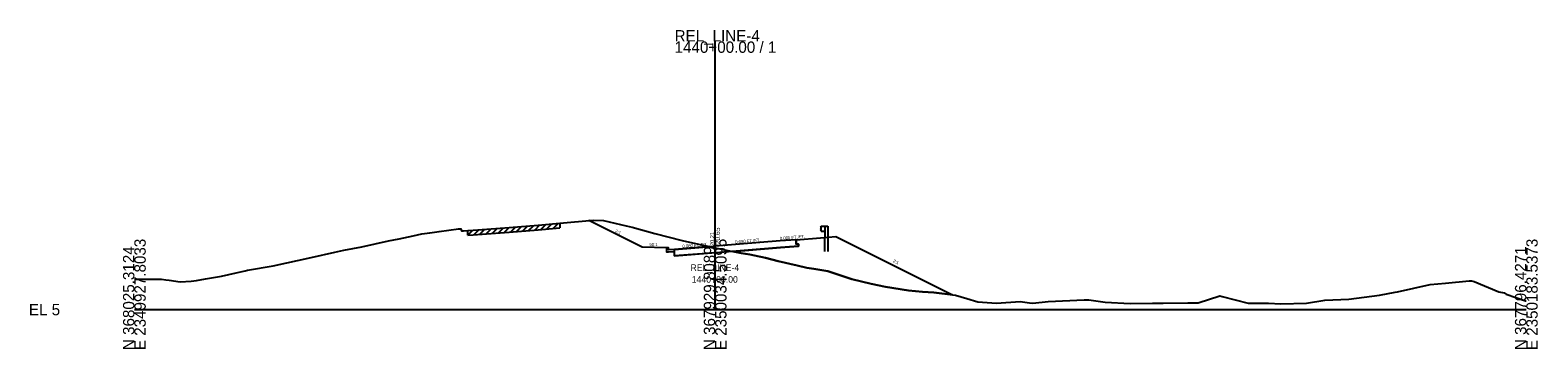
# Model space of a CAD drawing. Extents: x -26 to 2350146, y -10 to 368200.
# Drawn here: x 1974.3 to 2346, y 1490.3 to 1569 of the extents above; entities that cross this region are included whole.
import ezdxf

# ---------------------------------------------------------------- set-up
doc = ezdxf.new("R2010")
doc.units = 0
for name, color, linetype in [('RD_GPK_XS_Cell', 7, 'Continuous'), ('RD_XS_Base', 7, 'Continuous'), ('RD_XS_CurbBase', 7, 'Continuous'), ('RD_XS_CurbFront', 7, 'Continuous'), ('RD_XS_CurbTop', 7, 'Continuous'), ('RD_XS_EarthShd', 7, 'Continuous'), ('RD_XS_EwShp', 7, 'Continuous'), ('RD_XS_ExGround', 7, 'Continuous'), ('RD_XS_ExPaveRet', 7, 'Continuous'), ('RD_XS_GR', 7, 'Continuous'), ('RD_XS_Pave', 7, 'Continuous'), ('RD_XS_PaveShd', 7, 'Continuous'), ('RD_XS_TieSlope', 7, 'Continuous'), ('RD_XS_TX_Elev_EX', 7, 'Continuous'), ('RD_XS_TX_Elev_PR', 7, 'Continuous'), ('RD_XS_TX_Slope', 7, 'Continuous'), ('RD_XS_TX_Station', 7, 'Continuous'), ('RD_XS_TX_TOC', 7, 'Continuous')]:
    doc.layers.add(name, color=color, linetype=linetype)

msp = doc.modelspace()

# ---------------------------------------------------------------- linework, layer by layer
at = {"layer": 'RD_GPK_XS_Cell'}
for p, q in [((2143.2, 1500), (2143.2, 1566.16)), ((2000, 1500), (2143.2, 1500)), ((2143.2, 1500), (2343.2, 1500))]:
    msp.add_line(p, q, dxfattribs=at)
at = {"layer": 'RD_XS_Base'}
for p, q in [((2163.21, 1517.25), (2163.21, 1516.11)), ((2143.33, 1514.02), (2133.2, 1513.21)), ((2159.33, 1515.3), (2143.33, 1514.02)), ((2163.71, 1515.65), (2159.33, 1515.3)), ((2163.71, 1516.15), (2163.71, 1515.65))]:
    msp.add_line(p, q, dxfattribs=at)
at = {"layer": 'RD_XS_CurbBase'}
for p, q in [((2131.2, 1515.25), (2131.2, 1514.25)), ((2131.2, 1514.25), (2131.7, 1514.25)), ((2131.7, 1514.25), (2133.2, 1514.33)), ((2133.2, 1513.27), (2133.2, 1514.33)), ((2163.71, 1516.15), (2163.21, 1516.11))]:
    msp.add_line(p, q, dxfattribs=at)
at = {"layer": 'RD_XS_CurbFront'}
msp.add_line((2133.2, 1514.33), (2133.2, 1514.83), dxfattribs=at)
at = {"layer": 'RD_XS_CurbTop'}
for p, q in [((2131.7, 1515.25), (2131.2, 1515.25)), ((2131.79, 1514.75), (2131.7, 1515.25)), ((2133.2, 1514.83), (2131.79, 1514.75)), ((2133.2, 1514.85), (2133.2, 1514.83))]:
    msp.add_line(p, q, dxfattribs=at)
at = {"layer": 'RD_XS_EarthShd'}
for p, q in [((2163.21, 1517.25), (2169.2, 1517.73)), ((2131.2, 1515.25), (2125.2, 1515.37))]:
    msp.add_line(p, q, dxfattribs=at)
at = {"layer": 'RD_XS_EwShp'}
for points in [[(2131.2, 1515.25), (2125.2, 1515.37), (2112.03, 1521.96), (2113.09, 1522.05), (2115.67, 1521.95), (2121.28, 1520.7), (2122.77, 1520.3), (2128.33, 1518.76), (2135.09, 1517.03), (2139.82, 1516), (2141.8, 1515.54), (2133.2, 1514.83), (2131.79, 1514.75), (2131.7, 1515.25)], [(2172.95, 1518.03), (2201.76, 1503.63), (2197.13, 1504.25), (2194.31, 1504.41), (2190.91, 1504.74), (2185.18, 1505.59), (2181.65, 1506.36), (2176.9, 1507.51), (2173.69, 1508.57), (2170.98, 1509.5), (2167.52, 1510.07), (2165.82, 1510.34), (2163.45, 1510.87), (2158.7, 1511.92), (2155.62, 1512.8), (2152.94, 1513.33), (2151.77, 1513.59), (2149.58, 1513.95), (2147.56, 1514.36), (2159.33, 1515.3), (2163.71, 1515.65), (2163.71, 1516.15), (2163.21, 1516.11), (2163.21, 1517.25), (2169.2, 1517.73)], [(2131.79, 1514.75), (2131.7, 1515.25), (2131.2, 1515.25), (2131.2, 1514.25), (2131.7, 1514.25), (2133.2, 1514.33), (2133.2, 1514.83)], [(2143.33, 1514.02), (2133.2, 1513.27), (2133.2, 1514.33), (2133.2, 1514.83), (2141.8, 1515.54), (2143.2, 1515.21), (2144.66, 1514.87), (2145.89, 1514.7), (2147.56, 1514.36)]]:
    msp.add_lwpolyline(points, close=True, dxfattribs=at)
at = {"layer": 'RD_XS_ExGround'}
msp.add_lwpolyline([(2000, 1507.49), (2006.71, 1507.49), (2007.78, 1507.37), (2008.59, 1507.29), (2011.33, 1506.86), (2014.03, 1507.03), (2015.31, 1507.18), (2017.55, 1507.63), (2021.5, 1508.28), (2025.12, 1509.04), (2027.34, 1509.58), (2027.93, 1509.69), (2034.21, 1510.77), (2043.63, 1512.82), (2049.43, 1514.14), (2051.67, 1514.69), (2056.07, 1515.5), (2062.62, 1516.97), (2065.28, 1517.5), (2068.73, 1518.24), (2070.87, 1518.68), (2072.85, 1518.96), (2075.17, 1519.27), (2079.96, 1519.91), (2080.49, 1519.92), (2080.65, 1519.42), (2081.13, 1519.45), (2082.22, 1519.52), (2083.52, 1519.61), (2092.45, 1520.23), (2099.55, 1520.86), (2104.9, 1521.31), (2113.09, 1522.05), (2115.67, 1521.95), (2121.28, 1520.7), (2122.77, 1520.3), (2128.33, 1518.76), (2135.09, 1517.03), (2139.82, 1516), (2143.2, 1515.21), (2144.66, 1514.87), (2145.89, 1514.7), (2149.58, 1513.95), (2151.77, 1513.59), (2152.94, 1513.33), (2155.62, 1512.8), (2158.7, 1511.92), (2163.45, 1510.87), (2165.82, 1510.34), (2167.52, 1510.07), (2170.98, 1509.5), (2173.69, 1508.57), (2176.9, 1507.51), (2181.65, 1506.36), (2185.18, 1505.59), (2190.91, 1504.74), (2194.31, 1504.41), (2197.13, 1504.25), (2202.49, 1503.53), (2205.26, 1502.73), (2207.97, 1501.92), (2212.54, 1501.6), (2218.37, 1501.97), (2220.73, 1501.7), (2221.51, 1501.58), (2225.27, 1502.03), (2234.18, 1502.39), (2234.82, 1502.42), (2235.33, 1502.43), (2239.36, 1501.84), (2245.51, 1501.5), (2251.06, 1501.56), (2253.63, 1501.58), (2259.75, 1501.69), (2260.89, 1501.69), (2262.33, 1501.67), (2267.67, 1503.39), (2268.25, 1503.27), (2274.64, 1501.62), (2279.67, 1501.56), (2282.69, 1501.45), (2288.97, 1501.62), (2293.55, 1502.36), (2299.45, 1502.55), (2306.97, 1503.56), (2310.89, 1504.28), (2311.44, 1504.39), (2319.49, 1506.17), (2323.29, 1506.51), (2329.1, 1507.13), (2329.7, 1507.1), (2330.37, 1506.94), (2336.43, 1504.41), (2337.73, 1504.17), (2338.24, 1503.81), (2342.99, 1502.13), (2343.2, 1502.14)], dxfattribs=at)
at = {"layer": 'RD_XS_ExPaveRet'}
for p, q in [((2094.22, 1519.24), (2095.48, 1520.5)), ((2095.72, 1519.38), (2096.98, 1520.63)), ((2097.22, 1519.51), (2098.48, 1520.77)), ((2098.72, 1519.64), (2099.97, 1520.9)), ((2100.22, 1519.77), (2101.47, 1521.02)), ((2101.72, 1519.9), (2102.97, 1521.15)), ((2103.22, 1520.02), (2104.47, 1521.27)), ((2104.9, 1521.31), (2104.9, 1520.16)), ((2082.22, 1518.37), (2083.45, 1519.6)), ((2082.22, 1518.37), (2082.22, 1519.52)), ((2082.22, 1518.37), (2083.52, 1518.46)), ((2083.52, 1518.46), (2092.45, 1519.09)), ((2083.72, 1518.48), (2084.95, 1519.71)), ((2085.22, 1518.58), (2086.45, 1519.81)), ((2086.72, 1518.69), (2087.95, 1519.91)), ((2088.22, 1518.79), (2089.45, 1520.02)), ((2089.72, 1518.89), (2090.95, 1520.12)), ((2091.22, 1519), (2092.45, 1520.23)), ((2092.45, 1519.09), (2099.55, 1519.72)), ((2092.72, 1519.11), (2093.98, 1520.36)), ((2099.55, 1519.72), (2104.9, 1520.16))]:
    msp.add_line(p, q, dxfattribs=at)
at = {"layer": 'RD_XS_GR'}
for p, q in [((2169.36, 1520.48), (2169.2, 1520.28)), ((2169.36, 1520.55), (2170.28, 1520.55)), ((2169.36, 1519.38), (2169.36, 1520.55)), ((2170.28, 1520.55), (2170.95, 1520.55)), ((2170.28, 1520.55), (2170.28, 1517.81)), ((2170.95, 1520.55), (2170.95, 1517.75)), ((2169.2, 1520.28), (2169.2, 1520.23)), ((2169.2, 1520.23), (2169.36, 1520.03)), ((2169.2, 1519.71), (2169.36, 1519.91)), ((2169.2, 1519.66), (2169.2, 1519.71)), ((2169.36, 1519.46), (2169.2, 1519.66)), ((2169.36, 1519.38), (2170.28, 1519.38)), ((2170.28, 1514.34), (2170.28, 1517.81)), ((2170.95, 1517.75), (2170.95, 1514.34))]:
    msp.add_line(p, q, dxfattribs=at)
at = {"layer": 'RD_XS_Pave'}
for p in [(2159.2, 1516.93), (2133.2, 1514.85)]:
    msp.add_line(p, (2143.2, 1515.65), dxfattribs=at)
at = {"layer": 'RD_XS_PaveShd'}
msp.add_line((2163.21, 1517.25), (2159.2, 1516.93), dxfattribs=at)
at = {"layer": 'RD_XS_TieSlope'}
for p, q in [((2125.2, 1515.37), (2112.03, 1521.96)), ((2169.2, 1517.73), (2172.95, 1518.03)), ((2172.95, 1518.03), (2201.76, 1503.63))]:
    msp.add_line(p, q, dxfattribs=at)

# ---------------------------------------------------------------- texts
at = {"layer": 'RD_GPK_XS_Cell'}
for s, p in [('REL_LINE-4', (2133.2, 1566.16)), ('1440+00.00 / 1', (2133.2, 1563.36)), ('EL 5', (1974, 1498.6))]:
    msp.add_text(s, height=2.8, dxfattribs=at).set_placement(p)
for s, p in [('E 2349927.8033', (2002.8, 1490)), ('E 2350034.5095', (2146, 1490)), ('E 2350183.5373', (2346, 1490)), ('N 368025.3124', (2000, 1490)), ('N 367929.8089', (2143.2, 1490)), ('N 367796.4271', (2343.2, 1490))]:
    msp.add_text(s, height=2.8, rotation=90, dxfattribs=at).set_placement(p)
at = {"layer": 'RD_XS_TX_Elev_EX'}
msp.add_text('20.21', height=1, rotation=90, dxfattribs=at).set_placement((2142.94, 1515.69))
at = {"layer": 'RD_XS_TX_Elev_PR'}
msp.add_text(' 20.65', height=1.2, rotation=90, dxfattribs=at).set_placement((2144.4, 1515.65))
at = {"layer": 'RD_XS_TX_Slope'}
for s, rotation, p in [('2:1', 333.4349, (2118.47, 1519.16)), ('0.080 FT./FT.', 4.5739, (2148.16, 1516.3)), ('0.080 FT./FT.', 4.5739, (2159.16, 1517.18)), ('50:1', 358.8542, (2127, 1515.71)), ('0.080 FT./FT.', 4.5739, (2135.16, 1515.26)), ('2:1', 333.4349, (2186.96, 1511.75))]:
    msp.add_text(s, height=0.75, rotation=rotation, dxfattribs=at).set_placement(p)
at = {"layer": 'RD_XS_TX_Station'}
for s, p in [('REL_LINE-4', (2137.13, 1509.55)), ('1440+00.00', (2137.43, 1506.65))]:
    msp.add_text(s, height=1.6, dxfattribs=at).set_placement(p)
at = {"layer": 'RD_XS_TX_TOC'}
msp.add_text('TOCLT', height=0.05, dxfattribs=at).set_placement((2131.75, 1515.2))

doc.saveas('drawing.dxf')
